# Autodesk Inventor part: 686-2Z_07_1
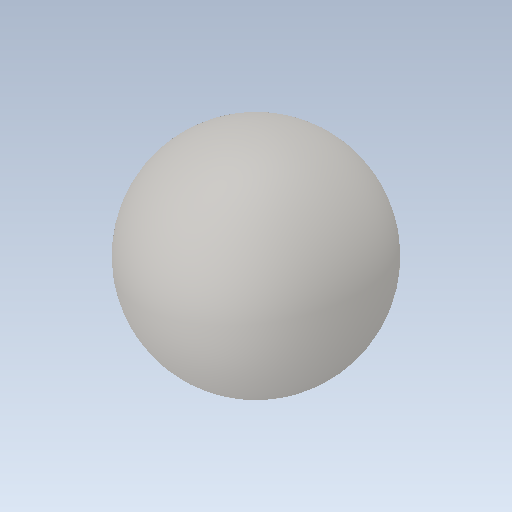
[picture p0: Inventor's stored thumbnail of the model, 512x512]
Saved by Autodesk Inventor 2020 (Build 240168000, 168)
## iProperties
Created: 2017-11
Part Number: 686-2Z_07_1
Material: Ogólny
Document SubType Name: Modeling
Designer: Tomasz
Density: 1 g/cm^3
Appearance: Domyślna
Sending System: SolidWorks 2017
Last Author: Tomasz
Last Saved: 2017-11-19
Source: 686-2Z_07_1
Author: Tomasz
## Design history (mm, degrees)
feature "Imported1"
node "Bryła1"
